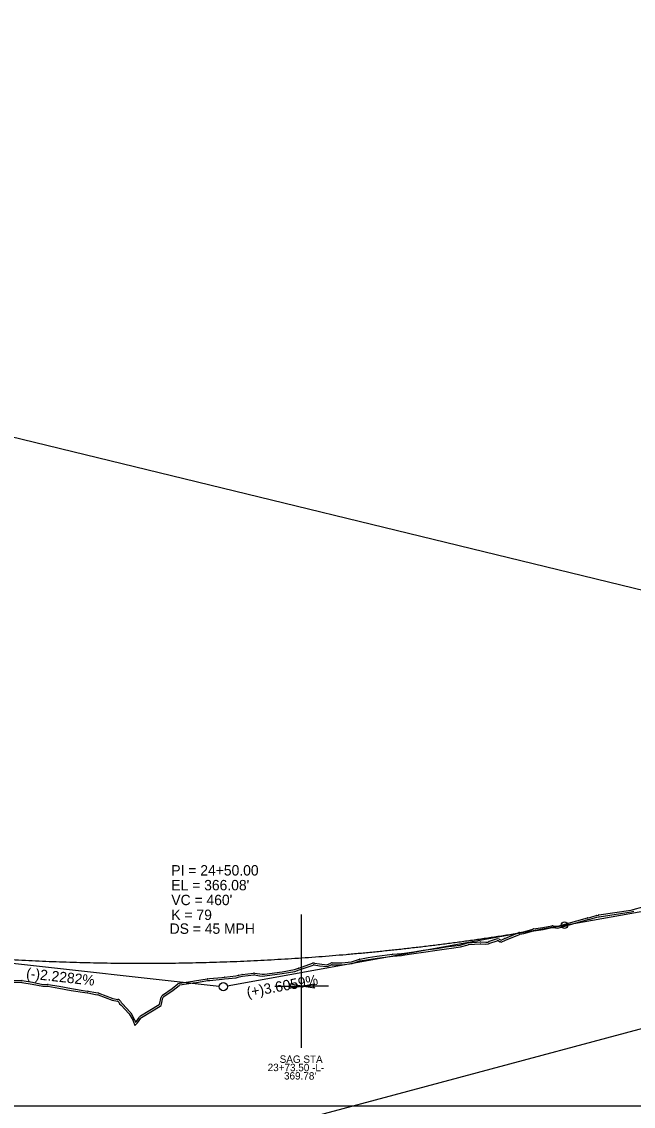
# Model space of a CAD drawing. Extents: x 1625686 to 1640492, y 1161393 to 1175642.
# Drawn here: x 1637226 to 1637638, y 1174911 to 1175642 of the extents above; entities that cross this region are included whole.
import ezdxf

# ---------------------------------------------------------------- set-up
doc = ezdxf.new("R2010")
doc.units = 0
for name, color, linetype in [('Exist Profile Cell', 7, 'Continuous'), ('Prop Plan Preparation Sag', 7, 'Continuous'), ('Prop Vertical Profile Curve Label', 7, 'Continuous'), ('Prop Vertical Profile Grade', 7, 'Continuous'), ('Prop Vertical Profile Grade Label', 7, 'Continuous'), ('Prop VPI Label', 7, 'Continuous'), ('Scratch_Level_1', 7, 'Continuous'), ('Scratch_Level_3', 7, 'Continuous')]:
    doc.layers.add(name, color=color, linetype=linetype)

msp = doc.modelspace()

# ---------------------------------------------------------------- linework, layer by layer
at = {"layer": 'Exist Profile Cell'}
msp.add_line((1635911.78, 1174910.79), (1640378.1, 1174910.79), dxfattribs=at)
at = {"layer": 'Prop Plan Preparation Sag'}
for p, q in [((1637414.61, 1174949.88), (1637414.61, 1175039.83)), ((1637396.61, 1174991.6), (1637414.61, 1174991.6)), ((1637432.61, 1174991.6), (1637414.61, 1174991.6))]:
    msp.add_line(p, q, dxfattribs=at)
for points in [[(1637406.05, 1174990.18), (1637414.61, 1174991.6), (1637406.05, 1174993.03), (1637407.11, 1174991.6)], [(1637423.18, 1174990.18), (1637414.61, 1174991.6), (1637423.18, 1174993.03), (1637422.11, 1174991.6)]]:
    msp.add_lwpolyline(points, close=True, dxfattribs=at)
at = {"layer": 'Prop Vertical Profile Curve Label'}
msp.add_circle((1637591.78, 1175032.65), 2.25, dxfattribs=at)
at = {"layer": 'Prop Vertical Profile Grade'}
msp.add_line((1637591.78, 1175032.65), (1637731.78, 1175057.9), dxfattribs=at)
msp.add_spline([(1637131.78, 1175016.81), (1637140.98, 1175015.81), (1637150.18, 1175014.87), (1637159.38, 1175013.98), (1637168.58, 1175013.14), (1637177.78, 1175012.36), (1637186.98, 1175011.63), (1637196.18, 1175010.95), (1637205.38, 1175010.33), (1637214.58, 1175009.76), (1637223.78, 1175009.25), (1637232.98, 1175008.78), (1637242.18, 1175008.38), (1637251.38, 1175008.02), (1637260.58, 1175007.72), (1637269.78, 1175007.47), (1637278.98, 1175007.28), (1637288.18, 1175007.14), (1637297.38, 1175007.06), (1637306.58, 1175007.02), (1637315.78, 1175007.05), (1637324.98, 1175007.12), (1637334.18, 1175007.25), (1637343.38, 1175007.43), (1637352.58, 1175007.67), (1637361.78, 1175007.96), (1637370.98, 1175008.3), (1637380.18, 1175008.7), (1637389.38, 1175009.15), (1637398.58, 1175009.66), (1637407.78, 1175010.21), (1637416.98, 1175010.83), (1637426.18, 1175011.49), (1637435.38, 1175012.21), (1637444.58, 1175012.99), (1637453.78, 1175013.81), (1637462.98, 1175014.69), (1637472.18, 1175015.63), (1637481.38, 1175016.61), (1637490.58, 1175017.66), (1637499.78, 1175018.75), (1637508.98, 1175019.9), (1637518.18, 1175021.1), (1637527.38, 1175022.36), (1637536.58, 1175023.67), (1637545.78, 1175025.03), (1637554.98, 1175026.45), (1637564.18, 1175027.92), (1637573.38, 1175029.44), (1637582.58, 1175031.02), (1637591.78, 1175032.65)], degree=3, dxfattribs=at)
at = {"layer": 'Prop VPI Label'}
for p, q in [((1637591.78, 1175032.65), (1637364.49, 1174991.67)), ((1637131.78, 1175016.81), (1637359.05, 1174991.49))]:
    msp.add_line(p, q, dxfattribs=at)
msp.add_circle((1637361.78, 1174991.19), 2.75, dxfattribs=at)
at = {"layer": 'Scratch_Level_1'}
for p, q in [((1637638.17, 1175043.3), (1637651.09, 1175046.76)), ((1637613.35, 1175039.23), (1637614.72, 1175039.55)), ((1637613.63, 1175038.02), (1637615, 1175038.33)), ((1637526.93, 1175020.8), (1637535.08, 1175021.4)), ((1637541.18, 1175021.81), (1637545.96, 1175023.37)), ((1637541.57, 1175020.62), (1637546.34, 1175022.18)), ((1637547.26, 1175022.12), (1637548.51, 1175021.54)), ((1637551.53, 1175023.81), (1637560.99, 1175027.66)), ((1637552, 1175022.65), (1637561.47, 1175026.51)), ((1637512.08, 1175018.04), (1637515.44, 1175018.52)), ((1637512.26, 1175016.8), (1637515.61, 1175017.28)), ((1637527.03, 1175019.56), (1637535.17, 1175020.15)), ((1637412.63, 1175003.76), (1637421.99, 1175007)), ((1637453.82, 1175009.8), (1637459.34, 1175010.86)), ((1637454.06, 1175008.57), (1637459.58, 1175009.63)), ((1637459.45, 1175010.87), (1637465.25, 1175011.72)), ((1637459.63, 1175009.64), (1637465.43, 1175010.48)), ((1637465.3, 1175011.72), (1637475.91, 1175013.05)), ((1637465.45, 1175010.48), (1637476.06, 1175011.81)), ((1637372.28, 1174999.03), (1637374.38, 1174999.46)), ((1637374.58, 1174999.49), (1637382.25, 1175000.41)), ((1637374.73, 1174998.25), (1637382.4, 1174999.17)), ((1637382.74, 1174999.17), (1637386.14, 1174998.64)), ((1637382.93, 1175000.4), (1637386.33, 1174999.88)), ((1637413.03, 1175002.58), (1637422.4, 1175005.81)), ((1637226.1, 1174994.13), (1637232.85, 1174992.95)), ((1637226.31, 1174995.37), (1637233.07, 1174994.18)), ((1637243.72, 1174992.76), (1637251.19, 1174991.46)), ((1637342.37, 1174995.15), (1637350.96, 1174996.52)), ((1637342.57, 1174993.91), (1637351.16, 1174995.29)), ((1637372.53, 1174997.81), (1637374.63, 1174998.24)), ((1637243.5, 1174991.53), (1637250.97, 1174990.22)), ((1637292.84, 1174978.75), (1637298.21, 1174973.11)), ((1637293.74, 1174979.61), (1637299.11, 1174973.97)), ((1637298.39, 1174972.86), (1637300.93, 1174968.35)), ((1637299.48, 1174973.48), (1637302.02, 1174968.96))]:
    msp.add_line(p, q, dxfattribs=at)
for points in [[(1637614.9, 1175039.58), (1637636.59, 1175042.92), (1637637.32, 1175043.06), (1637638.14, 1175043.29)], [(1637583.95, 1175031.06), (1637587.33, 1175030.72), (1637607.62, 1175036.48)], [(1637584.08, 1175032.3), (1637587.22, 1175031.98), (1637607.28, 1175037.68)], [(1637607.54, 1175037.74), (1637608.86, 1175037.97), (1637610.21, 1175038.33), (1637613.21, 1175039.2)], [(1637607.75, 1175036.51), (1637609.12, 1175036.74), (1637610.54, 1175037.12), (1637613.56, 1175038)], [(1637615.09, 1175038.35), (1637636.81, 1175041.69), (1637637.61, 1175041.85), (1637638.48, 1175042.09)], [(1637561.55, 1175027.82), (1637564.12, 1175028.23), (1637570.49, 1175030.08)], [(1637561.74, 1175026.58), (1637564.39, 1175027), (1637570.84, 1175028.87)], [(1637570.83, 1175030.15), (1637577.15, 1175031.05), (1637583.34, 1175032.27)], [(1637571.01, 1175028.91), (1637577.36, 1175029.82), (1637583.58, 1175031.04)], [(1637535.46, 1175021.4), (1637538.66, 1175021.14), (1637540.21, 1175021.34), (1637540.79, 1175021.65)], [(1637547.78, 1175023.26), (1637549.02, 1175022.68), (1637551.45, 1175023.77)], [(1637548.57, 1175021.51), (1637548.99, 1175021.29), (1637551.96, 1175022.63)], [(1637476.01, 1175013.06), (1637481.86, 1175013.55), (1637484.01, 1175013.82), (1637490.12, 1175014.73), (1637496.58, 1175015.73)], [(1637476.11, 1175011.82), (1637481.99, 1175012.31), (1637484.18, 1175012.58), (1637490.31, 1175013.49), (1637496.77, 1175014.49)], [(1637496.6, 1175015.73), (1637505.7, 1175017.04), (1637512.05, 1175018.03)], [(1637496.78, 1175014.49), (1637505.89, 1175015.8), (1637512.24, 1175016.8)], [(1637515.51, 1175018.53), (1637521.52, 1175019.22), (1637526.39, 1175020.7)], [(1637515.65, 1175017.29), (1637521.78, 1175018), (1637526.75, 1175019.5)], [(1637535.36, 1175020.15), (1637538.69, 1175019.89), (1637540.59, 1175020.13), (1637541.37, 1175020.54)], [(1637423.16, 1175007.11), (1637426.73, 1175006.6), (1637431.58, 1175006.01), (1637434.25, 1175007.09)], [(1637435.2, 1175006.02), (1637441.75, 1175005.96), (1637448.58, 1175006.85), (1637453.91, 1175008.54)], [(1637435.21, 1175007.27), (1637441.67, 1175007.21), (1637448.31, 1175008.07), (1637453.54, 1175009.73)], [(1637362.52, 1174997.66), (1637370.32, 1174998.48), (1637372.09, 1174998.99)], [(1637386.18, 1174998.63), (1637387.92, 1174998.29), (1637389.77, 1174998.51), (1637401.56, 1175000.1), (1637410.08, 1175001.51), (1637413.02, 1175002.57)], [(1637386.42, 1174999.86), (1637387.97, 1174999.56), (1637389.62, 1174999.75), (1637401.37, 1175001.34), (1637409.77, 1175002.73), (1637412.59, 1175003.75)], [(1637422.98, 1175005.87), (1637426.57, 1175005.36), (1637431.75, 1175004.74), (1637434.72, 1175005.93)], [(1637211.16, 1174994.94), (1637218.29, 1174994.25), (1637225.9, 1174994.15)], [(1637211.28, 1174996.18), (1637218.35, 1174995.5), (1637225.91, 1174995.4)], [(1637232.88, 1174992.95), (1637240.11, 1174991.54), (1637243.28, 1174991.55)], [(1637233.12, 1174994.18), (1637240.23, 1174992.79), (1637243.28, 1174992.8)], [(1637320.92, 1174985.59), (1637327.34, 1174989.92), (1637331.18, 1174993.06)], [(1637321.62, 1174984.55), (1637328.08, 1174988.91), (1637331.97, 1174992.09)], [(1637332.38, 1174993.59), (1637341.24, 1174994.96), (1637342.36, 1174995.15)], [(1637332.57, 1174992.36), (1637341.43, 1174993.73), (1637342.56, 1174993.91)], [(1637351.23, 1174996.55), (1637352.58, 1174996.62), (1637360.79, 1174997.43), (1637362.44, 1174997.65)], [(1637351.29, 1174995.3), (1637352.68, 1174995.37), (1637360.93, 1174996.19), (1637362.61, 1174996.42)], [(1637362.65, 1174996.42), (1637370.56, 1174997.24), (1637372.44, 1174997.79)], [(1637250.99, 1174990.22), (1637259.22, 1174988.68), (1637268.53, 1174987.24), (1637270.31, 1174987.03)], [(1637251.22, 1174991.45), (1637259.43, 1174989.91), (1637268.69, 1174988.48), (1637270.45, 1174988.28)], [(1637270.41, 1174987.02), (1637275.68, 1174985.96), (1637277.17, 1174985.74)], [(1637270.66, 1174988.24), (1637275.89, 1174987.19), (1637277.35, 1174986.98)], [(1637277.44, 1174985.67), (1637286.89, 1174982.04), (1637290.47, 1174981.44)], [(1637277.89, 1174986.84), (1637287.23, 1174983.25), (1637290.67, 1174982.67)], [(1637291.37, 1174980.78), (1637291.92, 1174979.71), (1637292.84, 1174978.75)], [(1637292.48, 1174981.35), (1637292.95, 1174980.44), (1637293.74, 1174979.62)], [(1637306, 1174971.46), (1637318.62, 1174979.1), (1637318.82, 1174979.26), (1637319.88, 1174984.06)], [(1637306.65, 1174970.39), (1637319.34, 1174978.07), (1637319.9, 1174978.53), (1637319.95, 1174978.59), (1637321.1, 1174983.79)], [(1637302.19, 1174968.59), (1637302.7, 1174967.2), (1637303.04, 1174967.55), (1637305.24, 1174970.74)], [(1637302.46, 1174965.2), (1637304.01, 1174966.75), (1637306.27, 1174970.03)], [(1637301.02, 1174968.16), (1637302.12, 1174965.13), (1637302.38, 1174965.18)]]:
    msp.add_lwpolyline(points, dxfattribs=at)
for centre, radius, start, end in [((1637638.81, 1175040.89), 2.5, 104.97241, 105.66396), ((1637607.96, 1175035.28), 2.5, 99.65702, 105.86842), ((1637607.96, 1175035.28), 1.25, 99.65702, 105.86842), ((1637613.91, 1175036.8), 2.5, 102.97479, 106.18399), ((1637613.91, 1175036.8), 1.25, 102.97479, 106.18399), ((1637615.28, 1175037.11), 2.5, 98.73652, 102.97479), ((1637615.28, 1175037.11), 1.25, 98.73652, 102.97479), ((1637571.19, 1175027.67), 2.5, 98.12002, 106.18405), ((1637571.19, 1175027.67), 1.25, 98.12002, 106.18405), ((1637583.82, 1175029.81), 2.5, 84.2188, 101.12186), ((1637583.82, 1175029.81), 1.25, 84.2188, 101.12186), ((1637527.12, 1175018.31), 2.5, 94.18432, 106.87919), ((1637535.26, 1175018.9), 2.5, 85.46991, 94.18432), ((1637541.95, 1175019.43), 2.5, 108.01865, 117.71627), ((1637546.73, 1175020.99), 2.5, 65.08241, 108.01865), ((1637546.73, 1175020.99), 1.25, 65.08241, 108.01865), ((1637547.99, 1175020.41), 1.25, 62.38392, 65.08241), ((1637552.48, 1175021.49), 2.5, 112.18347, 114.21941), ((1637552.48, 1175021.49), 1.25, 112.18347, 114.21941), ((1637561.94, 1175025.35), 2.5, 98.99015, 112.18347), ((1637561.94, 1175025.35), 1.25, 98.99015, 112.18347), ((1637496.96, 1175013.26), 2.5, 98.17392, 98.81894), ((1637496.96, 1175013.26), 1.25, 98.17392, 98.81894), ((1637512.44, 1175015.56), 2.5, 98.17473, 98.91782), ((1637512.44, 1175015.56), 1.25, 98.17473, 98.91782), ((1637515.79, 1175016.05), 2.5, 96.57943, 98.17473), ((1637515.79, 1175016.05), 1.25, 96.57943, 98.17473), ((1637527.12, 1175018.31), 1.25, 94.18432, 106.87919), ((1637535.26, 1175018.9), 1.25, 85.46991, 94.18432), ((1637541.95, 1175019.43), 1.25, 108.01865, 117.71627), ((1637422.81, 1175004.63), 2.5, 81.98765, 109.0462), ((1637435.18, 1175004.77), 2.5, 89.46482, 111.96063), ((1637454.29, 1175007.35), 2.5, 100.80776, 107.58312), ((1637454.29, 1175007.35), 1.25, 100.80776, 107.58312), ((1637459.81, 1175008.4), 2.5, 98.28779, 100.80776), ((1637459.81, 1175008.4), 1.25, 98.28779, 100.80776), ((1637465.61, 1175009.24), 2.5, 97.12572, 98.28779), ((1637465.61, 1175009.24), 1.25, 97.12572, 98.28779), ((1637476.22, 1175010.57), 2.5, 94.81661, 97.12572), ((1637476.22, 1175010.57), 1.25, 94.81661, 97.12572), ((1637372.78, 1174996.58), 2.5, 101.49071, 106.10396), ((1637374.88, 1174997.01), 2.5, 96.83488, 101.49071), ((1637382.55, 1174997.93), 2.5, 81.23095, 96.83488), ((1637382.55, 1174997.93), 1.25, 81.23095, 96.83488), ((1637385.95, 1174997.41), 2.5, 79.00352, 81.23095), ((1637413.44, 1175001.4), 2.5, 109.0462, 109.85653), ((1637413.44, 1175001.4), 1.25, 109.0462, 109.85653), ((1637422.81, 1175004.63), 1.25, 81.98765, 109.0462), ((1637435.18, 1175004.77), 1.25, 89.46482, 111.96063), ((1637225.88, 1174992.9), 1.25, 80.07584, 89.286), ((1637225.88, 1174992.9), 2.5, 80.07584, 89.286), ((1637232.64, 1174991.72), 1.25, 78.96953, 80.07584), ((1637232.64, 1174991.72), 2.5, 78.96953, 80.07584), ((1637243.29, 1174990.3), 2.5, 80.09387, 90.16619), ((1637243.29, 1174990.3), 1.25, 80.09387, 90.16619), ((1637332.76, 1174991.12), 2.5, 98.77027, 129.26062), ((1637332.76, 1174991.12), 1.25, 98.77027, 129.26062), ((1637342.77, 1174992.68), 2.5, 99.09632, 99.43101), ((1637342.77, 1174992.68), 1.25, 99.09632, 99.43101), ((1637351.35, 1174994.05), 2.5, 92.92433, 99.09632), ((1637351.35, 1174994.05), 1.25, 92.92433, 99.09632), ((1637362.78, 1174995.18), 2.5, 95.94344, 97.75035), ((1637362.78, 1174995.18), 1.25, 95.94344, 97.75035), ((1637372.78, 1174996.58), 1.25, 101.49071, 106.10396), ((1637374.88, 1174997.01), 1.25, 96.83488, 101.49071), ((1637385.95, 1174997.41), 1.25, 79.00352, 81.23095), ((1637250.76, 1174988.99), 1.25, 79.39938, 80.09387), ((1637250.76, 1174988.99), 2.5, 79.39938, 80.09387), ((1637270.16, 1174985.79), 1.25, 78.62729, 83.35432), ((1637270.16, 1174985.79), 2.5, 78.62729, 83.35432), ((1637276.99, 1174984.51), 1.25, 68.98376, 81.80576), ((1637276.99, 1174984.51), 2.5, 68.98376, 81.80576), ((1637322.32, 1174983.52), 2.5, 124.03065, 167.48028), ((1637322.32, 1174983.52), 1.25, 124.03065, 167.48028), ((1637290.26, 1174980.2), 1.25, 27.3473, 80.36966), ((1637290.26, 1174980.2), 2.5, 27.3473, 80.36966), ((1637291.93, 1174977.89), 1.25, 43.60206, 43.7404), ((1637291.93, 1174977.89), 2.5, 43.60206, 43.7404), ((1637297.3, 1174972.25), 1.25, 29.38599, 43.60206), ((1637297.3, 1174972.25), 2.5, 29.38599, 43.60206), ((1637307.3, 1174969.32), 2.5, 121.19009, 145.4726), ((1637307.3, 1174969.32), 1.25, 121.19009, 145.4726), ((1637299.84, 1174967.73), 1.25, 20.00874, 29.38599), ((1637299.84, 1174967.73), 2.5, 20.00874, 29.38599), ((1637302.65, 1174963.97), 1.25, 98.84356, 102.65426)]:
    msp.add_arc(centre, radius, start, end, dxfattribs=at)
at = {"layer": 'Scratch_Level_3'}
for p, q in [((1636069.38, 1175641.97), (1640127.74, 1174654.21)), ((1636080.34, 1174544.46), (1640138.71, 1175631))]:
    msp.add_line(p, q, dxfattribs=at)
msp.add_lwpolyline([(1635911.78, 1174910.79), (1640049.19, 1174910.79), (1640049.19, 1175362.47)], dxfattribs=at)

# ---------------------------------------------------------------- texts
at = {"layer": 'Prop Plan Preparation Sag'}
for s, p in [('SAG STA', (1637399.78, 1174939.86)), ('23+73.50 -L-', (1637391.69, 1174934.29)), ("369.78'", (1637402.71, 1174928.63))]:
    msp.add_text(s, height=5, rotation=359.75466, dxfattribs=at).set_placement(p)
at = {"layer": 'Prop Vertical Profile Curve Label'}
for s, p in [("VC = 460'", (1637326.78, 1175046.19)), ('K = 79', (1637326.78, 1175036.19)), ('DS = 45 MPH', (1637325.63, 1175026.86))]:
    msp.add_text(s, height=7, dxfattribs=at).set_placement(p)
at = {"layer": 'Prop Vertical Profile Grade Label'}
for s, rotation, p in [('(-)2.2282%', 353.64279, (1637228.64, 1174996.96)), ('(+)3.6059%', 10.2203, (1637378.19, 1174983.98))]:
    msp.add_text(s, height=7, rotation=rotation, dxfattribs=at).set_placement(p)
at = {"layer": 'Prop VPI Label'}
for s, p in [('PI = 24+50.00', (1637326.78, 1175066.19)), ("EL = 366.08'", (1637326.78, 1175056.19))]:
    msp.add_text(s, height=7, dxfattribs=at).set_placement(p)

doc.saveas('drawing.dxf')
